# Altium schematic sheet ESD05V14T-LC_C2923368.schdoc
size 127 x 101 mm
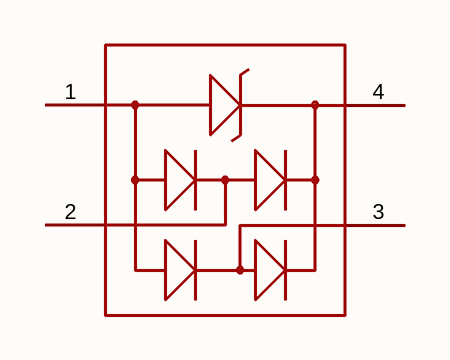
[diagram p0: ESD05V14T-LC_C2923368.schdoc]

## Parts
D?  esd05v14t-lc  [SOT-143_L2.9-W1.3-P1.92-LS2.3-BL]  (value not drawn)

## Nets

Not connected (* = marked no-connect by the designer): D? 1 2 3 4

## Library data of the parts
D? = esd05v14t-lc: 极性:单向;反向截止电压(Vrwm):5V;钳位电压:15V;峰值脉冲电流(Ipp):6A@8/20us;峰值脉冲功率(Ppp):100W@8/20us;击穿电压:6.5V;; Manufacturer: TECH PUBLIC(台舟); Symbol: ESD05V14T-LC_C2923368; AddInBom: yes; ModelId: 2f65c54dcf124ea98761abb8aba517da; ModelTransform: 91.04793,118.11,0,270,0,0,0,0,0; Polarity: 单向; Reverse Stand-Off Voltage (Vrwm): 5V; Clamping Voltage: 15V; Voltage - Breakdown: 6.5V; Reverse Leakage Current (Ir): 80nA; Number of Channels: 三路; level of protection: IEC 61000-4-2；IEC 61000-4-4；IEC 61000-4-5; Type: ESD; Junction Capacitance: 0.8pF；0.3pF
